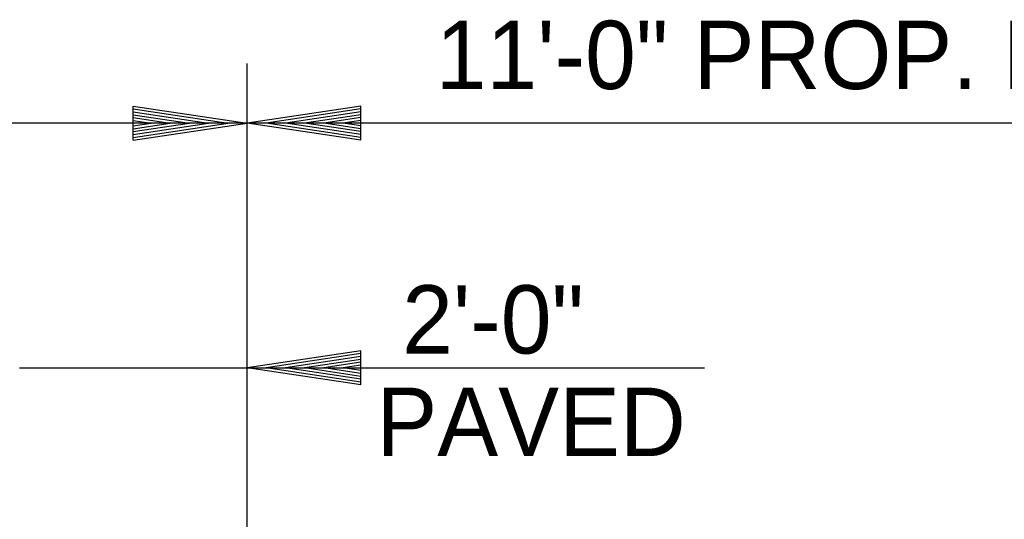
# Model space of a CAD drawing. Extents: x 2829243 to 2838161, y 467639 to 474695.
# Drawn here: x 2833661.9 to 2833748.5, y 469091.5 to 469135.4 of the extents above; entities that cross this region are included whole.
import ezdxf

# ---------------------------------------------------------------- set-up
doc = ezdxf.new("R2010")
doc.units = 0
doc.layers.add('R_Dimension', color=7, linetype='Continuous')
doc.layers.add('R_Draft', color=7, linetype='Continuous')

msp = doc.modelspace()

# ---------------------------------------------------------------- linework, layer by layer
at = {"layer": 'R_Dimension'}
for p, q in [((2833681.9, 469075.825), (2833681.9, 469131.569)), ((2833671.9, 469127.818), (2833681.9, 469126.318)), ((2833671.9, 469124.818), (2833671.9, 469127.818)), ((2833691.9, 469127.818), (2833681.9, 469126.318)), ((2833691.9, 469124.818), (2833691.9, 469127.818)), ((2833671.9, 469127.568), (2833680.23, 469126.318)), ((2833671.9, 469127.313), (2833678.51, 469126.318)), ((2833671.9, 469127.063), (2833676.845, 469126.318)), ((2833691.9, 469127.568), (2833683.57, 469126.318)), ((2833691.9, 469127.313), (2833685.29, 469126.318)), ((2833691.9, 469127.063), (2833686.955, 469126.318)), ((2833681.9, 469126.318), (2833641.9, 469126.318)), ((2833671.9, 469126.808), (2833675.15, 469126.318)), ((2833671.9, 469126.553), (2833673.48, 469126.318)), ((2833671.9, 469124.818), (2833681.9, 469126.318)), ((2833671.9, 469125.833), (2833675.15, 469126.318)), ((2833671.9, 469125.323), (2833678.51, 469126.318)), ((2833671.9, 469125.068), (2833680.23, 469126.318)), ((2833671.9, 469125.573), (2833676.845, 469126.318)), ((2833671.9, 469126.083), (2833673.48, 469126.318)), ((2833691.9, 469124.818), (2833681.9, 469126.318)), ((2833791.9, 469126.318), (2833681.9, 469126.318)), ((2833691.9, 469125.068), (2833683.57, 469126.318)), ((2833691.9, 469125.323), (2833685.29, 469126.318)), ((2833691.9, 469125.573), (2833686.955, 469126.318)), ((2833691.9, 469126.808), (2833688.65, 469126.318)), ((2833691.9, 469125.833), (2833688.65, 469126.318)), ((2833691.9, 469126.553), (2833690.32, 469126.318)), ((2833691.9, 469126.083), (2833690.32, 469126.318))]:
    msp.add_line(p, q, dxfattribs=at)
at = {"layer": 'R_Draft'}
for p, q in [((2833691.9, 469106.323), (2833681.9, 469104.823)), ((2833691.9, 469103.323), (2833691.9, 469106.323)), ((2833691.9, 469106.073), (2833683.57, 469104.823)), ((2833691.9, 469105.818), (2833685.29, 469104.823)), ((2833691.9, 469105.568), (2833686.955, 469104.823)), ((2833691.9, 469105.313), (2833688.65, 469104.823)), ((2833661.9, 469104.823), (2833722.119, 469104.823)), ((2833691.9, 469103.323), (2833681.9, 469104.823)), ((2833691.9, 469103.573), (2833683.57, 469104.823)), ((2833691.9, 469103.828), (2833685.29, 469104.823)), ((2833691.9, 469104.078), (2833686.955, 469104.823)), ((2833691.9, 469104.338), (2833688.65, 469104.823)), ((2833691.9, 469105.058), (2833690.32, 469104.823)), ((2833691.9, 469104.588), (2833690.32, 469104.823))]:
    msp.add_line(p, q, dxfattribs=at)

# ---------------------------------------------------------------- texts
at = {"layer": 'R_Dimension'}
msp.add_text('11\'-0" PROP. LANE', height=6, dxfattribs=at).set_placement((2833698.49, 469129.318))
at = {"layer": 'R_Draft'}
for s, p in [('2\'-0"', (2833695.541, 469106.083)), ('PAVED', (2833693.273, 469097.083))]:
    msp.add_text(s, height=6, dxfattribs=at).set_placement(p)

doc.saveas('drawing.dxf')
